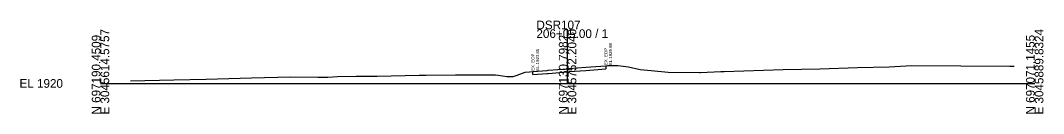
# Model space of a CAD drawing. Extents: x -26 to 19003, y -31 to 24541.
# Drawn here: x 1974.3 to 2302.8, y 7990.3 to 8020.2 of the extents above; entities that cross this region are included whole.
import ezdxf

# ---------------------------------------------------------------- set-up
doc = ezdxf.new("R2010")
doc.units = 0
for name, color, linetype in [('DESIGN - SHEET - Light Grid', 7, 'Continuous'), ('SURVEY - GROUND - Existing Pavement Layer', 7, 'Continuous'), ('SURVEY - GROUND - Existing Pavement Text', 7, 'Continuous'), ('SURVEY - GROUND - Top of Ground', 7, 'Continuous')]:
    doc.layers.add(name, color=color, linetype=linetype)

msp = doc.modelspace()

# ---------------------------------------------------------------- linework, layer by layer
at = {"layer": 'DESIGN - SHEET - Light Grid'}
for p, q in [((2150, 8000), (2150, 8017.4)), ((2000, 8000), (2150, 8000)), ((2150, 8000), (2300, 8000))]:
    msp.add_line(p, q, dxfattribs=at)
at = {"layer": 'SURVEY - GROUND - Existing Pavement Layer'}
for p, q in [((2138.85, 8002.85), (2138.85, 8003.85)), ((2138.85, 8002.85), (2143.4, 8003.2)), ((2143.4, 8003.2), (2143.77, 8003.23)), ((2143.77, 8003.23), (2150, 8003.74)), ((2150, 8003.74), (2150.55, 8003.78)), ((2150.55, 8003.78), (2155.89, 8004.2)), ((2155.89, 8004.2), (2162.28, 8004.69)), ((2162.28, 8005.69), (2162.28, 8004.69))]:
    msp.add_line(p, q, dxfattribs=at)
at = {"layer": 'SURVEY - GROUND - Top of Ground'}
msp.add_lwpolyline([(2009.63, 8000.84), (2023.59, 8001.12), (2033.96, 8001.37), (2048.51, 8001.75), (2061.15, 8002.08), (2069.75, 8002.02), (2072.97, 8002.06), (2076.14, 8002.22), (2082.16, 8002.38), (2082.75, 8002.38), (2088.87, 8002.33), (2102.33, 8002.62), (2103.19, 8002.63), (2104.56, 8002.63), (2114.05, 8002.72), (2119.64, 8002.75), (2120.25, 8002.76), (2123.14, 8002.78), (2126.8, 8002.78), (2127.7, 8002.68), (2130.48, 8002.24), (2132.14, 8002.25), (2132.54, 8002.26), (2133.84, 8002.67), (2136.37, 8003.57), (2137.72, 8003.72), (2138.85, 8003.85), (2143.4, 8004.2), (2143.77, 8004.23), (2150, 8004.74), (2150.55, 8004.78), (2155.89, 8005.2), (2162.28, 8005.69), (2162.84, 8005.72), (2163.48, 8005.76), (2164.78, 8005.75), (2166.11, 8005.73), (2169.6, 8005.29), (2173.26, 8004.51), (2176.86, 8004.18), (2182.27, 8003.65), (2192.31, 8003.52), (2192.7, 8003.55), (2199.26, 8003.82), (2200.28, 8003.88), (2219.25, 8004.43), (2231.03, 8004.66), (2243.06, 8005.1), (2253.25, 8005.38), (2260.52, 8005.8), (2292.01, 8005.57), (2293.41, 8005.52)], dxfattribs=at)

# ---------------------------------------------------------------- texts
at = {"layer": 'DESIGN - SHEET - Light Grid'}
for s, p in [('DSR107', (2140, 8017.4)), ('206+05.00 / 1', (2140, 8014.6)), ('EL 1920', (1974, 7998.6))]:
    msp.add_text(s, height=2.8, dxfattribs=at).set_placement(p)
for s, p in [('E 3045614.5757', (2002.8, 7990)), ('E 3045752.2040', (2152.8, 7990)), ('E 3045889.8324', (2302.8, 7990)), ('N 697190.4509', (2000, 7990)), ('N 697130.7982', (2150, 7990)), ('N 697071.1455', (2300, 7990))]:
    msp.add_text(s, height=2.8, rotation=90, dxfattribs=at).set_placement(p)
at = {"layer": 'SURVEY - GROUND - Existing Pavement Text'}
for s, p in [('EL.1923.85', (2140.85, 8004.05)), ('EX. EOP', (2162.78, 8005.89)), ('EL.1925.69', (2164.28, 8005.89)), ('EX. EOP', (2139.35, 8004.05))]:
    msp.add_text(s, height=1, rotation=90, dxfattribs=at).set_placement(p)

doc.saveas('drawing.dxf')
